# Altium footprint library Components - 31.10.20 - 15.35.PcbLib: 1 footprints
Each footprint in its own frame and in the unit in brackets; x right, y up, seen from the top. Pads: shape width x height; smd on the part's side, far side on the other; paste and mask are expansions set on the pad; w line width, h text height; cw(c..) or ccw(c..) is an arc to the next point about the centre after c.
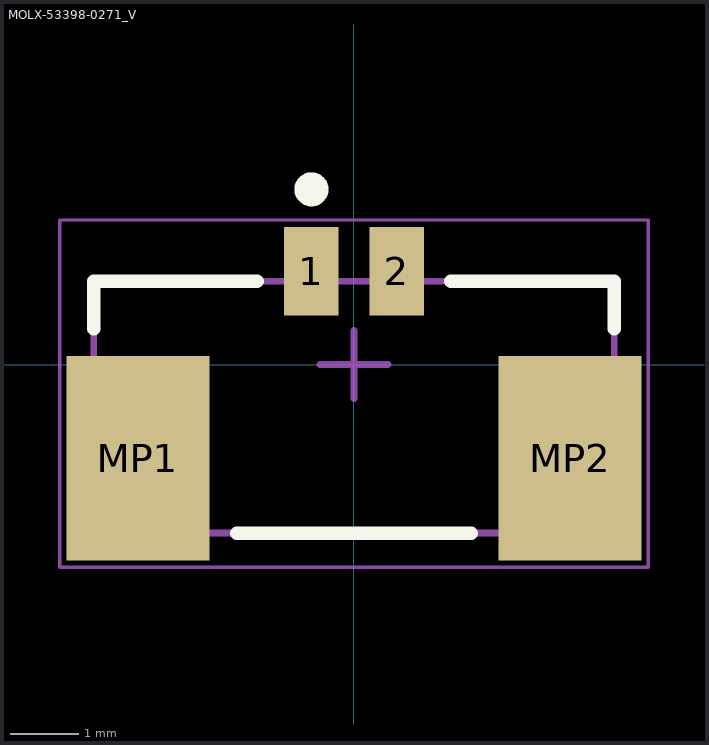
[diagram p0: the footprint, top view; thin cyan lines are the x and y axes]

## MOLX-53398-0271_V [mm] "Header, 2-Leads, Body 7.65x3.7mm, Pitch 1.25mm"
height 4.7
pads (4):
  rect 0.8x1.3 smd: 1(-0.625,1.375) 2(0.625,1.375)
  rect 2.1x3 smd: MP1(-3.175,-1.375) MP2(3.175,-1.375)
Top Overlay:
  circle w0.25: c-0.625,2.575 r0.125
  lines w0.2: -3.825,0.525 -3.825,1.225 -1.425,1.225 ; -1.725,-2.475 1.725,-2.475 ; 1.425,1.225 3.825,1.225 3.825,0.525
Mechanical 13:
  lines w0.1: -3.825,-2.475 -3.825,1.225 3.825,1.225 3.825,-2.475 -3.825,-2.475
Mechanical 15:
  lines w0.05: -4.325,-2.975 4.325,-2.975 4.325,2.125 -4.325,2.125 -4.325,-2.975
  lines w0.1: -0.5,0 0.5,0 ; 0,-0.5 0,0.5
3D body "533980271.stp": height 4.72, standoff -0.02, extent -3.825,-2.489 3.825,1.711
